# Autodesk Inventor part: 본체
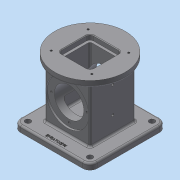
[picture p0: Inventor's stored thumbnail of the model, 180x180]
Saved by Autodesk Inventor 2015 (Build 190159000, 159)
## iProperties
Created: 2021-05
Part Number: 본체
Material: 일반
Document SubType Name: Modeling
Designer: 102879
Density: 1 g/cm^3
Appearance: 기본값
Author: 102879
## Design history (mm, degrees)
sketch "스케치1"
  geometry: L1 (37, -37)-(-37, -37); L2 (-37, -37)-(-37, 37); L3 (-37, 37)-(37, 37); L4 (37, 37)-(37, -37); L5 (37, -37)-(-37, 37); L6 (-37, -37)-(37, 37); 1 further point
  constraints: 12 end point, 2 midpoint, 2 parallel, 1 horizontal, 1 perpendicular
  dimensions: "d0" = 74 distance of L2.end L3.end; "d1" = 74 distance of L1.end L2.end
extrude "돌출1" new body sketch "스케치1" stored distance "d2" = 88; taper "d3" = 0 deg
sketch "스케치2"
  geometry: C1 r 57.5 at (0, 0); 1 further point
  constraints: 1 centre point, 1 coincident
  dimensions: "d4" = 115 diameter of C1
extrude "돌출2" join sketch "스케치2" distance "d5" = 10; taper "d6" = 0 deg
sketch "스케치3"
  geometry: L1 (-62.5, 62.5)-(62.5, 62.5); L2 (62.5, 62.5)-(62.5, -62.5); L3 (62.5, -62.5)-(-62.5, -62.5); L4 (-62.5, -62.5)-(-62.5, 62.5); L5 (-62.5, 62.5)-(62.5, -62.5); L6 (62.5, 62.5)-(-62.5, -62.5); 1 further point
  constraints: 12 end point, 2 midpoint, 2 parallel, 1 horizontal, 1 perpendicular
  dimensions: "d7" = 125 distance of L2.end L3.end; "d8" = 125 distance of L1.end L2.end
extrude "돌출3" join sketch "스케치3" distance "d9" = 10; taper "d10" = 0 deg
sketch "스케치4"
  geometry: L1 (44, 37)-(-44, 37) reference; L2 (0, 37)-(35, 37); L3 (35, 37)-(35, 34); L4 (35, 34)-(0, 34); L5 (0, 34)-(0, 37); L6 (0, 34)-(24, 34); L7 (24, 34)-(24, -34); L8 (24, -34)-(0, -34); L9 (0, -34)-(0, 34); L10 (-44, -37)-(44, -37) reference; L11 (0, -34)-(35, -34); L12 (35, -34)-(35, -37); L13 (35, -37)-(0, -37); L14 (0, -37)-(0, -34); 1 further point
  constraints: 24 end point, 6 parallel, 3 horizontal, 3 perpendicular, 2 point on line, 1 midpoint
  dimensions: "d11" = 70 diameter of L3 L9; "d12" = 48 diameter of L7 L9; "d13" = 3 distance between parallel lines of L1 L4; "d14" = 3 distance between parallel lines of L10 L8
revolve "회전1" sketch "스케치4" stored, may be unused: angle "d15" = 90 deg
sketch "스케치5" dims "d16" = 58
  geometry: C1 r 24 at (0, 0) reference; C2 r 35 at (0, 0) reference; 2 further points
  constraints: 2 vertical alignment, 1 coincident, 2 other
hole "구멍1" sketch "스케치5" at (0, 29) diameter "d17" = 3.242; stored, may be unused: countersink angle "d21" = 90 deg, drill point angle "d23" = 118 deg; dims "d18" = 8, "d19" = 4, "d20" = 2, "d22" = 10
sketch "스케치6"
  geometry: L1 (-22, -22)-(22, -22); L2 (22, -22)-(22, 22); L3 (22, 22)-(-22, 22); L4 (-22, 22)-(-22, -22); L5 (-22, -22)-(22, 22); L6 (22, -22)-(-22, 22); C1 r 57.5 at (0, 0) reference
  constraints: 12 end point, 2 midpoint, 2 parallel, 1 horizontal, 1 perpendicular
  dimensions: "d27" = 44 distance of L3.end L2.end; "d28" = 44 distance of L2.end L1.end
extrude "돌출4" cut sketch "스케치6" distance "d29" = 82; taper "d30" = 0 deg
sketch "스케치7"
  geometry: L1 (22, 22)-(22, -22) reference; L2 (22, -22)-(-22, -22) reference; L3 (-22, -22)-(-22, 22) reference; L4 (-22, 22)-(22, 22) reference; L5 (-26, -26)-(26, -26); L6 (26, -26)-(26, 26); L7 (26, 26)-(-26, 26); L8 (-26, 26)-(-26, -26); L9 (-26, -26)-(26, 26); L10 (26, -26)-(-26, 26); C1 r 57.5 at (0, 0) reference
  constraints: 12 end point, 2 midpoint, 2 parallel, 1 horizontal, 1 perpendicular
  dimensions: "d31" = 52 distance of L7.end L6.end; "d32" = 52 distance of L6.end L5.end
extrude "돌출5" cut sketch "스케치7" distance "d33" = 8; taper "d34" = 0 deg
fillet "모깎기1" dims "d35" = 3
fillet "모깎기2" dims "d36" = 3
fillet "모깎기3" dims "d37" = 6
chamfer "모따기1" distance "d38" = 1; stored, may be unused: second distance "d39" = 2, angle "d40" = 45 deg
fillet "모깎기4" dims "d41" = 3
fillet "모깎기5" dims "d42" = 3
fillet "모깎기6" dims "d43" = 12
sketch "스케치8"
  geometry: A1 r 12 centre (-50.5, -50.5) between (-62.5, -50.5) and (-50.5, -62.5) reference; A2 r 12 centre (50.5, -50.5) between (50.5, -62.5) and (62.5, -50.5) reference; A3 r 12 centre (50.5, 50.5) between (62.5, 50.5) and (50.5, 62.5) reference; A4 r 12 centre (-50.5, 50.5) between (-50.5, 62.5) and (-62.5, 50.5) reference; 1 further point
hole "구멍2" sketch "스케치8" at (-50.5, 50.5), (50.5, 50.5), (-50.5, -50.5), (50.5, -50.5) diameter "d44" = 9; stored, may be unused: countersink angle "d48" = 90 deg, drill point angle "d50" = 118 deg; dims "d45" = 8, "d46" = 4, "d47" = 2, "d49" = 10
sketch "스케치9"
  geometry: L1 (33, 30)-(-33, 30); L2 (-33, 30)-(-33, -30); L3 (-33, -30)-(33, -30); L4 (33, -30)-(33, 30); L5 (33, 30)-(-33, -30); L6 (-33, 30)-(33, -30); C1 r 57.5 at (0, 0) reference; 4 further points
  constraints: 12 end point, 4 coincident, 2 midpoint, 2 parallel, 1 horizontal, 1 perpendicular
  dimensions: "d51" = 66 distance of L3.end L2.end; "d52" = 60 distance of L2.end L1.end
hole "구멍3" sketch "스케치9" at (33, 30), (-33, 30), (33, -30), (-33, -30) diameter "d53" = 3.242; stored, may be unused: countersink angle "d57" = 90 deg, drill point angle "d59" = 118 deg; dims "d54" = 8, "d55" = 4, "d56" = 2, "d58" = 10
sketch "스케치10"
  geometry: L1 (84.5, -13)-(-16.5, -13) reference; 2 further points
  constraints: 1 vertical alignment
  dimensions: "d60" = 37 distance from line of L1 point (34, 24)
hole "구멍4" sketch "스케치10" at (34, 24) diameter "d62" = 4.134; stored, may be unused: countersink angle "d66" = 90 deg, drill point angle "d68" = 0 deg; dims "d63" = 10, "d64" = 4, "d65" = 2, "d67" = 14.2
sketch "스케치11"
  geometry: C1 r 2.067 at (34, 24) reference; 2 further points
  constraints: 1 vertical alignment
  dimensions: "d69" = 43 distance of C1.centre point (34, 67)
hole "구멍5" sketch "스케치11" at (34, 67) diameter "d70" = 4.134; stored, may be unused: countersink angle "d74" = 90 deg, drill point angle "d76" = 0 deg; dims "d71" = 10, "d72" = 4, "d73" = 2, "d75" = 14.2
sketch "스케치12"
  geometry: L1 (-54, -50.5)-(-54, 50.5) reference; L2 (-54, 0)-(-36, 0); L3 (-36, 0)-(-36, 24.826); L4 (-36, 24.826)-(-54, 28); L5 (-54, 0)-(-54, 28); 1 further point
  constraints: 8 end point, 1 horizontal, 1 midpoint, 1 parallel, 1 point on line, 1 vertical
  dimensions: "d77" = 18 distance of L2.start L2.end; "d78" = 80 deg angle of L1 L4; "d79" = 56 diameter of L4.end L2
revolve "회전2" sketch "스케치12" stored, may be unused: angle "d80" = 90 deg
fillet "모깎기7" dims "d81" = 3
node "작업 평면1"
sketch "스케치13"
  geometry: 2 further points
  constraints: 1 vertical alignment, 1 other
  dimensions: "d83" = 55 distance of point (0, 0) point (0, -55)
feature "엠보싱1" sketch "스케치13" dims "d0" = 74, "d1" = 74, "d84" = 0.5, "d85" = 0
node "솔리드1"
pattern_circular "원형 패턴1" dims angle "d25" = 360 deg
mirror "대칭1"
other parameters: "d82" = 5
